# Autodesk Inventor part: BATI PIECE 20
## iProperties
Created: 2004-11
Part Number: BATI PIECE 20
Document SubType Name: Modeling
Designer: Bruno
Manufacturer: Standard
Standards Organization: Custom
Author: Bruno
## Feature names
1. Base1
